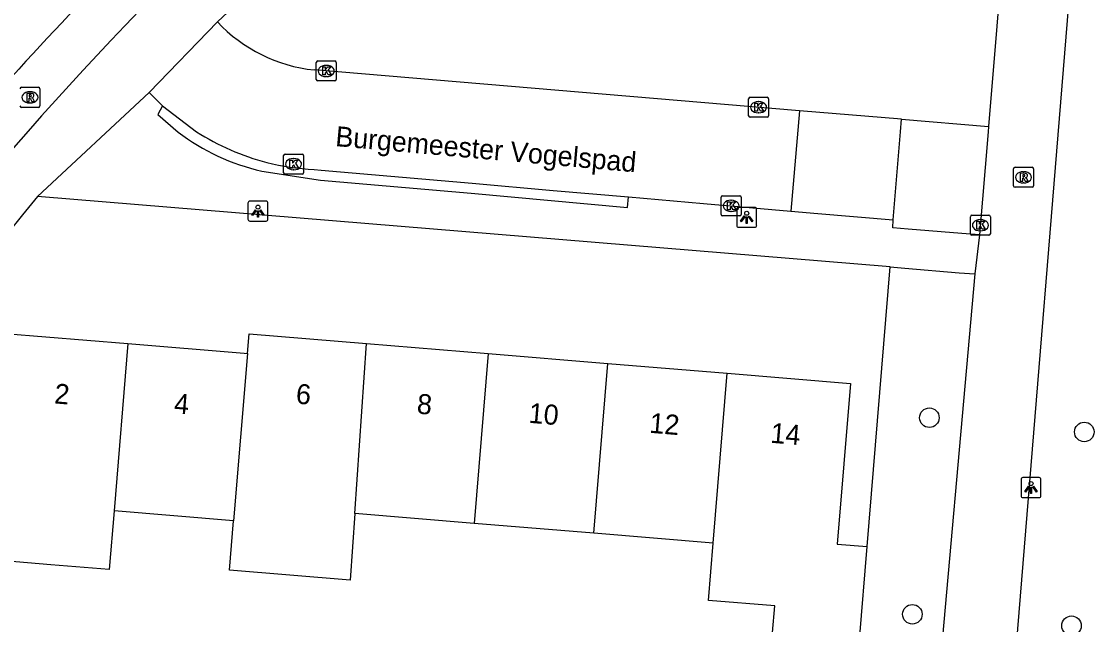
# Model space of a CAD drawing. Extents: x 159961 to 160856, y 382704 to 383353.
# Drawn here: x 160403.4 to 160457.1, y 383225.4 to 383255.5 of the extents above; entities that cross this region are included whole.
import ezdxf

# ---------------------------------------------------------------- set-up
doc = ezdxf.new("R2010")
doc.units = 0
for name, color, linetype in [('IMGEO_Boom', 7, 'Continuous'), ('IMGEO_Fietspad_open', 7, 'Continuous'), ('IMGEO_Groenvoorziening', 7, 'Continuous'), ('IMGEO_Kolk', 7, 'Continuous'), ('IMGEO_Lichtpunt', 7, 'Continuous'), ('IMGEO_Openbare_ruimte_label', 7, 'Continuous'), ('IMGEO_Pand', 7, 'Continuous'), ('IMGEO_Pand_nummerreeks', 7, 'Continuous'), ('IMGEO_Parkeervlak_gesloten', 7, 'Continuous'), ('IMGEO_Rijbaan_lokaal_open', 7, 'Continuous'), ('IMGEO_Rioolput', 7, 'Continuous'), ('IMGEO_Voetpad_open', 7, 'Continuous')]:
    doc.layers.add(name, color=color, linetype=linetype)

msp = doc.modelspace()

# ---------------------------------------------------------------- linework, layer by layer
at = {"layer": 'IMGEO_Boom'}
for centre in [(160448.803, 383235.72), (160456.55, 383235.009), (160447.951, 383225.896), (160455.91, 383225.326)]:
    msp.add_circle(centre, 0.489, dxfattribs=at)
at = {"layer": 'IMGEO_Fietspad_open'}
msp.add_lwpolyline([(160403.726, 383250.036), (160403.003, 383249.212)], dxfattribs=at)
for centre, radius, start, end in [((160534.83, 383134.449), 174.782, 127.83621, 138.59926), ((160525.006, 383142.407), 164.572, 133.31976, 139.17317)]:
    msp.add_arc(centre, radius, start, end, dxfattribs=at)
at = {"layer": 'IMGEO_Groenvoorziening'}
for points in [[(160447.403, 383250.634), (160451.763, 383250.268)], [(160445.692, 383229.286), (160446.838, 383243.253)]]:
    msp.add_lwpolyline(points, dxfattribs=at)
at = {"layer": 'IMGEO_Kolk'}
for p, q in [((160418.141, 383252.623), (160418.141, 383253.475)), ((160418.216, 383253.549), (160419.068, 383253.549)), ((160418.629, 383253.329), (160418.654, 383253.329)), ((160419.142, 383253.475), (160419.142, 383252.623)), ((160418.652, 383252.769), (160418.627, 383252.769)), ((160419.068, 383252.549), (160418.216, 383252.549)), ((160439.76, 383250.809), (160439.76, 383251.661)), ((160439.835, 383251.735), (160440.687, 383251.735)), ((160440.761, 383251.661), (160440.761, 383250.809)), ((160440.248, 383251.515), (160440.273, 383251.515)), ((160440.687, 383250.735), (160439.835, 383250.735)), ((160440.271, 383250.955), (160440.246, 383250.955)), ((160416.505, 383247.965), (160416.505, 383248.817)), ((160416.58, 383248.891), (160417.432, 383248.891)), ((160416.993, 383248.671), (160417.018, 383248.671)), ((160417.506, 383248.817), (160417.506, 383247.965)), ((160417.432, 383247.891), (160416.58, 383247.891)), ((160417.016, 383248.111), (160416.991, 383248.111)), ((160438.464, 383246.808), (160439.316, 383246.808)), ((160438.389, 383245.882), (160438.389, 383246.734)), ((160438.877, 383246.588), (160438.902, 383246.588)), ((160439.39, 383246.734), (160439.39, 383245.882)), ((160439.316, 383245.808), (160438.464, 383245.808)), ((160438.9, 383246.028), (160438.875, 383246.028)), ((160450.854, 383244.913), (160450.854, 383245.765)), ((160450.929, 383245.839), (160451.781, 383245.839)), ((160451.855, 383245.765), (160451.855, 383244.913)), ((160451.342, 383245.619), (160451.367, 383245.619)), ((160451.781, 383244.839), (160450.929, 383244.839)), ((160451.365, 383245.059), (160451.34, 383245.059))]:
    msp.add_line(p, q, dxfattribs=at)
for points in [[(160418.141, 383252.623), (160418.141, 383253.475)], [(160418.216, 383253.549), (160419.068, 383253.549)], [(160418.462, 383253.249), (160418.585, 383253.249), (160418.585, 383253.098), (160418.715, 383253.249), (160418.879, 383253.249), (160418.733, 383253.098), (160418.886, 383252.849), (160418.734, 383252.849), (160418.649, 383253.013), (160418.585, 383252.946), (160418.585, 383252.849), (160418.462, 383252.849), (160418.462, 383253.249)], [(160419.142, 383253.475), (160419.142, 383252.623)], [(160419.068, 383252.549), (160418.216, 383252.549)], [(160439.76, 383250.809), (160439.76, 383251.661)], [(160439.835, 383251.735), (160440.687, 383251.735)], [(160440.761, 383251.661), (160440.761, 383250.809)], [(160440.081, 383251.435), (160440.204, 383251.435), (160440.204, 383251.284), (160440.334, 383251.435), (160440.498, 383251.435), (160440.352, 383251.284), (160440.505, 383251.035), (160440.353, 383251.035), (160440.268, 383251.199), (160440.204, 383251.132), (160440.204, 383251.035), (160440.081, 383251.035), (160440.081, 383251.435)], [(160440.687, 383250.735), (160439.835, 383250.735)], [(160416.505, 383247.965), (160416.505, 383248.817)], [(160416.58, 383248.891), (160417.432, 383248.891)], [(160416.826, 383248.591), (160416.949, 383248.591), (160416.949, 383248.44), (160417.079, 383248.591), (160417.243, 383248.591), (160417.097, 383248.44), (160417.25, 383248.191), (160417.098, 383248.191), (160417.013, 383248.355), (160416.949, 383248.288), (160416.949, 383248.191), (160416.826, 383248.191), (160416.826, 383248.591)], [(160417.506, 383248.817), (160417.506, 383247.965)], [(160417.432, 383247.891), (160416.58, 383247.891)], [(160438.464, 383246.808), (160439.316, 383246.808)], [(160438.389, 383245.882), (160438.389, 383246.734)], [(160438.71, 383246.508), (160438.833, 383246.508), (160438.833, 383246.357), (160438.963, 383246.508), (160439.127, 383246.508), (160438.981, 383246.357), (160439.134, 383246.108), (160438.982, 383246.108), (160438.897, 383246.272), (160438.833, 383246.205), (160438.833, 383246.108), (160438.71, 383246.108), (160438.71, 383246.508)], [(160439.39, 383246.734), (160439.39, 383245.882)], [(160439.316, 383245.808), (160438.464, 383245.808)], [(160450.854, 383244.913), (160450.854, 383245.765)], [(160450.929, 383245.839), (160451.781, 383245.839)], [(160451.855, 383245.765), (160451.855, 383244.913)], [(160451.175, 383245.539), (160451.298, 383245.539), (160451.298, 383245.388), (160451.428, 383245.539), (160451.592, 383245.539), (160451.446, 383245.388), (160451.599, 383245.139), (160451.447, 383245.139), (160451.362, 383245.303), (160451.298, 383245.236), (160451.298, 383245.139), (160451.175, 383245.139), (160451.175, 383245.539)], [(160451.781, 383244.839), (160450.929, 383244.839)]]:
    msp.add_lwpolyline(points, dxfattribs=at)
for centre, start, end in [((160418.218, 383253.473), 91.552, 178.448), ((160418.218, 383253.473), 91.552, 178.448), ((160419.066, 383253.473), 1.552, 88.448), ((160419.066, 383253.473), 1.552, 88.448), ((160418.218, 383252.625), 181.552, 268.448), ((160418.218, 383252.625), 181.552, 268.448), ((160419.066, 383252.625), 271.552, 358.448), ((160419.066, 383252.625), 271.552, 358.448), ((160439.837, 383251.659), 91.552, 178.448), ((160439.837, 383251.659), 91.552, 178.448), ((160440.685, 383251.659), 1.552, 88.448), ((160440.685, 383251.659), 1.552, 88.448), ((160439.837, 383250.811), 181.552, 268.448), ((160439.837, 383250.811), 181.552, 268.448), ((160440.685, 383250.811), 271.552, 358.448), ((160440.685, 383250.811), 271.552, 358.448), ((160416.582, 383248.815), 91.552, 178.448), ((160416.582, 383248.815), 91.552, 178.448), ((160417.43, 383248.815), 1.552, 88.448), ((160417.43, 383248.815), 1.552, 88.448), ((160416.582, 383247.967), 181.552, 268.448), ((160416.582, 383247.967), 181.552, 268.448), ((160417.43, 383247.967), 271.552, 358.448), ((160417.43, 383247.967), 271.552, 358.448), ((160438.466, 383246.732), 91.552, 178.448), ((160438.466, 383246.732), 91.552, 178.448), ((160439.314, 383246.732), 1.552, 88.448), ((160439.314, 383246.732), 1.552, 88.448), ((160438.466, 383245.884), 181.552, 268.448), ((160438.466, 383245.884), 181.552, 268.448), ((160439.314, 383245.884), 271.552, 358.448), ((160439.314, 383245.884), 271.552, 358.448), ((160450.931, 383245.763), 91.552, 178.448), ((160450.931, 383245.763), 91.552, 178.448), ((160451.779, 383245.763), 1.552, 88.448), ((160451.779, 383245.763), 1.552, 88.448), ((160450.931, 383244.915), 181.552, 268.448), ((160450.931, 383244.915), 181.552, 268.448), ((160451.779, 383244.915), 271.552, 358.448), ((160451.779, 383244.915), 271.552, 358.448)]:
    msp.add_arc(centre, 0.0765, start, end, dxfattribs=at)
for centre, major_axis, ratio, start_param, end_param in [((160418.628, 383253.049), (-0.387, 0.002), 0.722429, 4.712389, 7.853982), ((160418.653, 383253.049), (-0.39, 0.002), 0.717154, 1.570796, 4.712389), ((160440.247, 383251.235), (-0.387, 0.002), 0.722429, 4.712389, 7.853982), ((160440.272, 383251.235), (-0.39, 0.002), 0.717154, 1.570796, 4.712389), ((160416.992, 383248.391), (-0.387, 0.002), 0.722429, 4.712389, 7.853982), ((160417.017, 383248.391), (-0.39, 0.002), 0.717154, 1.570796, 4.712389), ((160438.876, 383246.308), (-0.387, 0.002), 0.722429, 4.712389, 7.853982), ((160438.901, 383246.308), (-0.39, 0.002), 0.717154, 1.570796, 4.712389), ((160451.341, 383245.339), (-0.387, 0.002), 0.722429, 4.712389, 7.853982), ((160451.366, 383245.339), (-0.39, 0.002), 0.717154, 1.570796, 4.712389)]:
    msp.add_ellipse(centre, major_axis=major_axis, ratio=ratio, start_param=start_param, end_param=end_param, dxfattribs=at)
at = {"layer": 'IMGEO_Lichtpunt'}
for p, q in [((160414.725, 383246.446), (160414.725, 383245.639)), ((160414.725, 383246.446), (160414.725, 383245.639)), ((160415.627, 383246.541), (160414.819, 383246.541)), ((160415.627, 383246.541), (160414.819, 383246.541)), ((160415.721, 383245.639), (160415.721, 383246.446)), ((160415.721, 383245.639), (160415.721, 383246.446)), ((160439.169, 383246.137), (160439.169, 383245.33)), ((160439.169, 383246.137), (160439.169, 383245.33)), ((160440.071, 383246.232), (160439.263, 383246.232)), ((160440.071, 383246.232), (160439.263, 383246.232)), ((160440.165, 383245.33), (160440.165, 383246.137)), ((160440.165, 383245.33), (160440.165, 383246.137)), ((160414.819, 383245.545), (160415.627, 383245.545)), ((160414.819, 383245.545), (160415.627, 383245.545)), ((160439.263, 383245.236), (160440.071, 383245.236)), ((160439.263, 383245.236), (160440.071, 383245.236)), ((160453.387, 383232.631), (160453.387, 383231.824)), ((160453.387, 383232.631), (160453.387, 383231.824)), ((160454.289, 383232.726), (160453.481, 383232.726)), ((160454.289, 383232.726), (160453.481, 383232.726)), ((160454.383, 383231.824), (160454.383, 383232.631)), ((160454.383, 383231.824), (160454.383, 383232.631)), ((160453.481, 383231.73), (160454.289, 383231.73)), ((160453.481, 383231.73), (160454.289, 383231.73))]:
    msp.add_line(p, q, dxfattribs=at)
for points in [[(160415.099, 383246.11), (160415.138, 383246.082), (160414.95, 383245.82), (160414.912, 383245.847), (160415.099, 383246.11)], [(160415.201, 383246.062), (160415.248, 383246.062), (160415.248, 383245.74), (160415.201, 383245.74), (160415.201, 383246.062)], [(160415.311, 383246.082), (160415.349, 383246.109), (160415.536, 383245.847), (160415.497, 383245.819), (160415.311, 383246.082)], [(160439.543, 383245.801), (160439.582, 383245.773), (160439.394, 383245.511), (160439.356, 383245.538), (160439.543, 383245.801)], [(160439.645, 383245.753), (160439.692, 383245.753), (160439.692, 383245.431), (160439.645, 383245.431), (160439.645, 383245.753)], [(160439.755, 383245.773), (160439.793, 383245.8), (160439.98, 383245.538), (160439.941, 383245.51), (160439.755, 383245.773)], [(160453.761, 383232.295), (160453.8, 383232.267), (160453.612, 383232.005), (160453.574, 383232.032), (160453.761, 383232.295)], [(160453.863, 383232.247), (160453.91, 383232.247), (160453.91, 383231.925), (160453.863, 383231.925), (160453.863, 383232.247)], [(160453.973, 383232.267), (160454.011, 383232.294), (160454.198, 383232.032), (160454.159, 383232.004), (160453.973, 383232.267)]]:
    msp.add_lwpolyline(points, dxfattribs=at)
for centre in [(160415.224, 383246.244), (160439.668, 383245.935), (160453.886, 383232.429)]:
    msp.add_circle(centre, 0.0994, dxfattribs=at)
for centre, start, end in [((160414.819, 383246.446), 90, 180), ((160414.819, 383246.446), 90, 180), ((160415.627, 383246.446), 0, 90), ((160415.627, 383246.446), 0, 90), ((160439.263, 383246.137), 90, 180), ((160439.263, 383246.137), 90, 180), ((160440.071, 383246.137), 0, 90), ((160440.071, 383246.137), 0, 90), ((160414.819, 383245.639), 180, 270), ((160414.819, 383245.639), 180, 270), ((160415.627, 383245.639), 270, 0), ((160415.627, 383245.639), 270, 360), ((160439.263, 383245.33), 180, 270), ((160439.263, 383245.33), 180, 270), ((160440.071, 383245.33), 270, 0), ((160440.071, 383245.33), 270, 360), ((160453.481, 383232.631), 90, 180), ((160453.481, 383232.631), 90, 180), ((160454.289, 383232.631), 0, 90), ((160454.289, 383232.631), 0, 90), ((160453.481, 383231.824), 180, 270), ((160453.481, 383231.824), 180, 270), ((160454.289, 383231.824), 270, 0), ((160454.289, 383231.824), 270, 360)]:
    msp.add_arc(centre, 0.0946, start, end, dxfattribs=at)
at = {"layer": 'IMGEO_Pand'}
for points in [[(160408.027, 383231.058), (160407.786, 383228.134), (160404.863, 383228.376), (160401.936, 383228.618), (160401.495, 383223.274), (160398.03, 383223.56), (160398.638, 383230.929), (160401.809, 383230.668), (160402.572, 383239.93), (160408.717, 383239.423)], [(160414.696, 383238.931), (160414.777, 383239.91), (160420.654, 383239.425)], [(160408.717, 383239.423), (160408.027, 383231.058)], [(160408.717, 383239.423), (160414.534, 383238.944), (160414.696, 383238.931)], [(160420.061, 383230.933), (160420.654, 383239.425)], [(160420.654, 383239.425), (160426.737, 383238.924)], [(160414.696, 383238.931), (160414.007, 383230.564)], [(160426.737, 383238.924), (160426.039, 383230.44)], [(160426.737, 383238.924), (160432.716, 383238.431)], [(160432.017, 383229.947), (160432.716, 383238.431)], [(160432.716, 383238.431), (160438.696, 383237.938)], [(160437.997, 383229.454), (160438.696, 383237.938)], [(160438.696, 383237.938), (160444.857, 383237.43), (160444.197, 383229.408), (160445.692, 383229.286)], [(160414.007, 383230.564), (160408.027, 383231.058)], [(160420.061, 383230.933), (160419.829, 383227.605), (160413.804, 383228.102), (160414.007, 383230.564)], [(160426.039, 383230.44), (160420.061, 383230.933)], [(160432.017, 383229.947), (160426.039, 383230.44)], [(160437.997, 383229.454), (160432.017, 383229.947)], [(160445.309, 383224.622), (160440.965, 383224.979), (160441.075, 383226.317), (160437.761, 383226.591), (160437.997, 383229.454)], [(160445.309, 383224.622), (160445.692, 383229.286)]]:
    msp.add_lwpolyline(points, dxfattribs=at)
at = {"layer": 'IMGEO_Parkeervlak_gesloten'}
for points in [[(160447.403, 383250.634), (160442.313, 383251.061)], [(160447, 383245.602), (160447.353, 383250), (160447.403, 383250.634)]]:
    msp.add_lwpolyline(points, dxfattribs=at)
at = {"layer": 'IMGEO_Rijbaan_lokaal_open'}
for points in [[(160413.194, 383255.504), (160409.79, 383251.977)], [(160442.313, 383251.061), (160418.035, 383253.099)], [(160409.79, 383251.977), (160410.453, 383251.312)], [(160410.453, 383251.312), (160412.157, 383250)], [(160442.313, 383251.061), (160441.876, 383246.048)], [(160418.042, 383248.123), (160418.392, 383248.092), (160425.932, 383247.436), (160429.995, 383247.082), (160433.749, 383246.755)], [(160433.749, 383246.755), (160437.514, 383246.428), (160441.876, 383246.048)]]:
    msp.add_lwpolyline(points, dxfattribs=at)
for centre, radius, start, end in [((160418.841, 383260.797), 7.74, 223.1432, 264.0205), ((160418.687, 383260.265), 12.166, 237.5403, 255.6096), ((160418.654, 383260.275), 12.167, 255.7683, 267.116)]:
    msp.add_arc(centre, radius, start, end, dxfattribs=at)
at = {"layer": 'IMGEO_Rioolput'}
for p, q in [((160403.397, 383252.23), (160404.249, 383252.23)), ((160403.81, 383252.01), (160403.835, 383252.01)), ((160404.323, 383252.156), (160404.323, 383251.304)), ((160404.249, 383251.23), (160403.397, 383251.23)), ((160403.833, 383251.45), (160403.808, 383251.45)), ((160453.011, 383247.308), (160453.011, 383248.16)), ((160453.086, 383248.234), (160453.938, 383248.234)), ((160453.499, 383248.014), (160453.524, 383248.014)), ((160454.012, 383248.16), (160454.012, 383247.308)), ((160453.522, 383247.454), (160453.497, 383247.454)), ((160453.938, 383247.234), (160453.086, 383247.234))]:
    msp.add_line(p, q, dxfattribs=at)
for points in [[(160403.397, 383252.23), (160404.249, 383252.23)], [(160403.911, 383251.928), (160403.659, 383251.93), (160403.659, 383251.53)], [(160403.659, 383251.53), (160403.783, 383251.53), (160403.783, 383251.692), (160403.794, 383251.692)], [(160403.837, 383251.849), (160403.783, 383251.849), (160403.783, 383251.768)], [(160403.783, 383251.768), (160403.835, 383251.768)], [(160403.841, 383251.663), (160403.912, 383251.53), (160404.052, 383251.53), (160403.987, 383251.656)], [(160404.323, 383252.156), (160404.323, 383251.304)], [(160404.249, 383251.23), (160403.397, 383251.23)], [(160453.011, 383247.308), (160453.011, 383248.16)], [(160453.086, 383248.234), (160453.938, 383248.234)], [(160453.6, 383247.932), (160453.348, 383247.934), (160453.348, 383247.534)], [(160454.012, 383248.16), (160454.012, 383247.308)], [(160453.348, 383247.534), (160453.472, 383247.534), (160453.472, 383247.696), (160453.483, 383247.696)], [(160453.526, 383247.853), (160453.472, 383247.853), (160453.472, 383247.772)], [(160453.472, 383247.772), (160453.524, 383247.772)], [(160453.53, 383247.667), (160453.601, 383247.534), (160453.741, 383247.534), (160453.676, 383247.66)], [(160453.938, 383247.234), (160453.086, 383247.234)]]:
    msp.add_lwpolyline(points, dxfattribs=at)
for centre, radius, start, end in [((160403.399, 383252.154), 0.0765, 91.552, 178.448), ((160403.399, 383252.154), 0.0765, 91.552, 178.448), ((160404.247, 383252.154), 0.0765, 1.552, 88.448), ((160404.247, 383252.154), 0.0765, 1.552, 88.448), ((160403.793, 383251.639), 0.0533, 26.0293, 88.6989), ((160403.819, 383251.957), 0.19, 274.7715, 282.9687), ((160403.843, 383251.753), 0.0964, 77.0061, 93.1865), ((160403.857, 383251.81), 0.0378, 276.6634, 79.6772), ((160403.91, 383251.818), 0.109, 350.3612, 89.416), ((160403.908, 383251.818), 0.112, 277.5842, 350.9817), ((160403.892, 383251.603), 0.108, 29.5134, 73.7905), ((160403.399, 383251.306), 0.0765, 181.552, 268.448), ((160403.399, 383251.306), 0.0765, 181.552, 268.448), ((160404.247, 383251.306), 0.0765, 271.552, 358.448), ((160404.247, 383251.306), 0.0765, 271.552, 358.448), ((160453.088, 383248.158), 0.0765, 91.552, 178.448), ((160453.088, 383248.158), 0.0765, 91.552, 178.448), ((160453.599, 383247.822), 0.109, 350.3612, 89.416), ((160453.936, 383248.158), 0.0765, 1.552, 88.448), ((160453.936, 383248.158), 0.0765, 1.552, 88.448), ((160453.482, 383247.643), 0.0533, 26.0293, 88.6989), ((160453.508, 383247.961), 0.19, 274.7715, 282.9687), ((160453.532, 383247.757), 0.0964, 77.0061, 93.1865), ((160453.546, 383247.814), 0.0378, 276.6634, 79.6772), ((160453.597, 383247.822), 0.112, 277.5842, 350.9817), ((160453.581, 383247.607), 0.108, 29.5134, 73.7905), ((160453.088, 383247.31), 0.0765, 181.552, 268.448), ((160453.088, 383247.31), 0.0765, 181.552, 268.448), ((160453.936, 383247.31), 0.0765, 271.552, 358.448), ((160453.936, 383247.31), 0.0765, 271.552, 358.448)]:
    msp.add_arc(centre, radius, start, end, dxfattribs=at)
for centre, major_axis, ratio, start_param, end_param in [((160403.809, 383251.73), (-0.387, 0.002), 0.722429, 4.712389, 7.853982), ((160403.834, 383251.73), (-0.39, 0.002), 0.717154, 1.570796, 4.712389), ((160453.498, 383247.734), (-0.387, 0.002), 0.722429, 4.712389, 7.853982), ((160453.523, 383247.734), (-0.39, 0.002), 0.717154, 1.570796, 4.712389)]:
    msp.add_ellipse(centre, major_axis=major_axis, ratio=ratio, start_param=start_param, end_param=end_param, dxfattribs=at)
at = {"layer": 'IMGEO_Voetpad_open'}
for points in [[(160452.266, 383213.376), (160452.763, 383219.455), (160459.993, 383308.019)], [(160455.038, 383289.805), (160451.763, 383250.268)], [(160414.746, 383256.974), (160413.194, 383255.504)], [(160404.207, 383246.768), (160409.79, 383251.977)], [(160410.453, 383251.312), (160410.214, 383250.876), (160411.23, 383249.994)], [(160451.763, 383250.268), (160451.741, 383250), (160451.314, 383244.859)], [(160415.423, 383248.044), (160418.347, 383247.595), (160425.887, 383246.939), (160433.709, 383246.226), (160433.749, 383246.755)], [(160446.838, 383243.253), (160404.207, 383246.768)], [(160441.876, 383246.048), (160443.23, 383245.93), (160447, 383245.602)], [(160451.314, 383244.859), (160450.434, 383244.93), (160447.741, 383245.148), (160446.969, 383245.21), (160447, 383245.602)], [(160451.314, 383244.859), (160451.071, 383242.904)], [(160446.838, 383243.253), (160447.574, 383243.192), (160450.29, 383242.968), (160451.071, 383242.904)], [(160451.071, 383242.904), (160449.03, 383219.895), (160448.479, 383213.682)]]:
    msp.add_lwpolyline(points, dxfattribs=at)
for centre, radius, start, end in [((160417.736, 383258.501), 10.71, 232.5913, 257.5261), ((160487.423, 383176.996), 108.596, 140.02231, 179.7063)]:
    msp.add_arc(centre, radius, start, end, dxfattribs=at)

# ---------------------------------------------------------------- texts
at = {"layer": 'IMGEO_Openbare_ruimte_label'}
msp.add_text('Burgemeester Vogelspad', height=1, rotation=355.0079, dxfattribs=at).set_placement((160419.07, 383249.296))
at = {"layer": 'IMGEO_Pand_nummerreeks'}
for s, rotation, p in [('2', 355.2879, (160405.017, 383236.437)), ('6', 355.2903, (160417.096, 383236.428)), ('4', 355.2903, (160411, 383235.944)), ('8', 355.2875, (160423.148, 383235.929)), ('10', 355.2875, (160428.737, 383235.468)), ('12', 355.2875, (160434.779, 383234.97)), ('14', 355.2875, (160440.831, 383234.471))]:
    msp.add_text(s, height=1, rotation=rotation, dxfattribs=at).set_placement(p)

doc.saveas('drawing.dxf')
